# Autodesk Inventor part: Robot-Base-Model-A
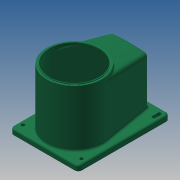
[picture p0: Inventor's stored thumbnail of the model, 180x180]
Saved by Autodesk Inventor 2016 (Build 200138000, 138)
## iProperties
Shininess: 21.0
Length Units: 11269
Angle Units: 11279
Time Units: 11290
Mass Units: 11283
Length Display Precision: 3
Angle Display Precision: 2
Created: 2001-08
Part Number: Robot-Base-Model-A
Document SubType Name: ﾓﾃﾞﾘﾝｸﾞ
Designer: Administrator
Density: 1 g/cm^3
Material: Generic
Mass: 357.513 g
Surface Area: 3582.83 cm^2
Volume: 357.513 cm^3
Appearance: Sea Green
Density: 0.0
Volumn: 0.0
Area: 0.0
PropertySet Name: Model Information
Control State: 0
Master: False
Checked Out: False
Author: Administrator
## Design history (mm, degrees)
node "Center-Work Plane"
fillet "Chamfer1" dims "d14" = 10
fillet "Chamfer2" dims "d15" = 5
fillet "Chamfer3" dims "d16" = 10
fillet "Chamfer4" dims "d30" = 5
sketch "Sketch6"
  geometry: L1 (80, 152.5)-(80, 137.5); L2 (84.5, 152.5)-(84.5, 137.5); L3 (75.5, 137.5)-(75.5, 152.5); L4 (-80, 152.5)-(-80, 137.5); L5 (-75.5, 152.5)-(-75.5, 137.5); L6 (-84.5, 137.5)-(-84.5, 152.5); A1 r 4.5 centre (80, 152.5) between (84.5, 152.5) and (75.5, 152.5); A2 r 4.5 centre (80, 137.5) between (75.5, 137.5) and (84.5, 137.5); A3 r 4.5 centre (-80, 152.5) between (-75.5, 152.5) and (-84.5, 152.5); A4 r 4.5 centre (-80, 137.5) between (-84.5, 137.5) and (-75.5, 137.5); 3 further points
  constraints: 16 end point, 8 point on circle, 8 tangent, 4 centre point, 4 parallel, 2 midpoint, 1 equal radius, 1 vertical
  dimensions: "d35" = 4.5 radius of A2; "d36" = 15 distance of L1.start L1.end
extrude "Extrusion5" cut sketch "Sketch6" stored distance "d37" = 10; taper "d38" = 0 deg
shell "Shell1" dims "d34" = 2
body "Solid1"
sketch "Sketch1"
  geometry: L1 (-93, 168)-(93, 168); L2 (93, 168)-(93, -82); L3 (93, -82)-(-93, -82); L4 (-93, -82)-(-93, 168); L5 (-93, 0)-(93, 0); L6 (0, 168)-(0, -82); 2 further points
  constraints: 12 end point, 3 midpoint, 3 point on line, 2 parallel, 1 coincident, 1 horizontal, 1 perpendicular, 1 other
  dimensions: "d0" = 250 distance of L3.end L1.start; "d1" = 186 distance of L1.start L1.end; "d2" = 82 distance between parallel lines of L3 L5
extrude "Extrusion1" new body sketch "Sketch1" distance "d3" = 15; taper "d4" = 0 deg
sketch "Sketch2"
  geometry: C1 r 75 at (0, 0)
  constraints: 1 centre point
  dimensions: "d5" = 150 diameter of C1
extrude "Extrusion2" join sketch "Sketch2" distance "d6" = 155; taper "d7" = 0 deg
sketch "Sketch3"
  geometry: L1 (-93, 168)-(93, 168) reference; L2 (-50, 153)-(50, 153); L3 (0, 197.064)-(0, -91.178); L4 (50, 153)-(73.933, 12.603); L5 (-50, 153)-(-73.933, 12.603); L6 (-73.933, 12.603)-(73.933, 12.603); A1 r 75 centre (0, 0) between (73.933, 12.603) and (-73.933, 12.603) reference
  constraints: 10 end point, 2 point on circle, 2 tangent, 1 parallel, 1 perpendicular, 1 point on line
  dimensions: "d8" = 50 distance from line of L2.start L3; "d9" = 50 distance from line of L2.end L3; "d10" = 15 distance between parallel lines of L2 L1
extrude "Extrusion3" join sketch "Sketch3" distance "d11" = 145; taper "d12" = 0 deg
feature "FaceDraft" dims angle "d13" = 10 deg
sketch "Sketch4"
  geometry: L1 (-93, -72)-(-93, 158) reference; L2 (-80, 145)-(80, 145); L3 (-80, 145)-(-80, -173.228); L4 (80, 145)-(80, -173.228); L5 (-80, -60)-(80, -60); L6 (0, 145)-(0, -60); 5 further points
  constraints: 10 end point, 4 coincident, 3 point on line, 2 midpoint, 2 parallel, 2 perpendicular, 1 other
  dimensions: "d19" = 160 distance between parallel lines of L4 L3; "d21" = 205 distance between parallel lines of L5 L2; "d22" = 60 distance from line of L5 point (0, 0)
hole "Hole1" sketch "Sketch4" diameter "d23" = 9; stored, may be unused: countersink angle "d27" = 82 deg, drill point angle "d29" = 118 deg; dims "d24" = 6, "d25" = 4, "d26" = 2, "d28" = 8
sketch "Sketch5"
  geometry: C1 r 75 at (0, 0) reference; C2 r 70 at (0, 0)
  constraints: 1 centre point
  dimensions: "d31" = 5 radial gap between concentric circles of C1 C2
extrude "Extrusion4" join sketch "Sketch5" distance "d32" = 2; taper "d33" = 0 deg
